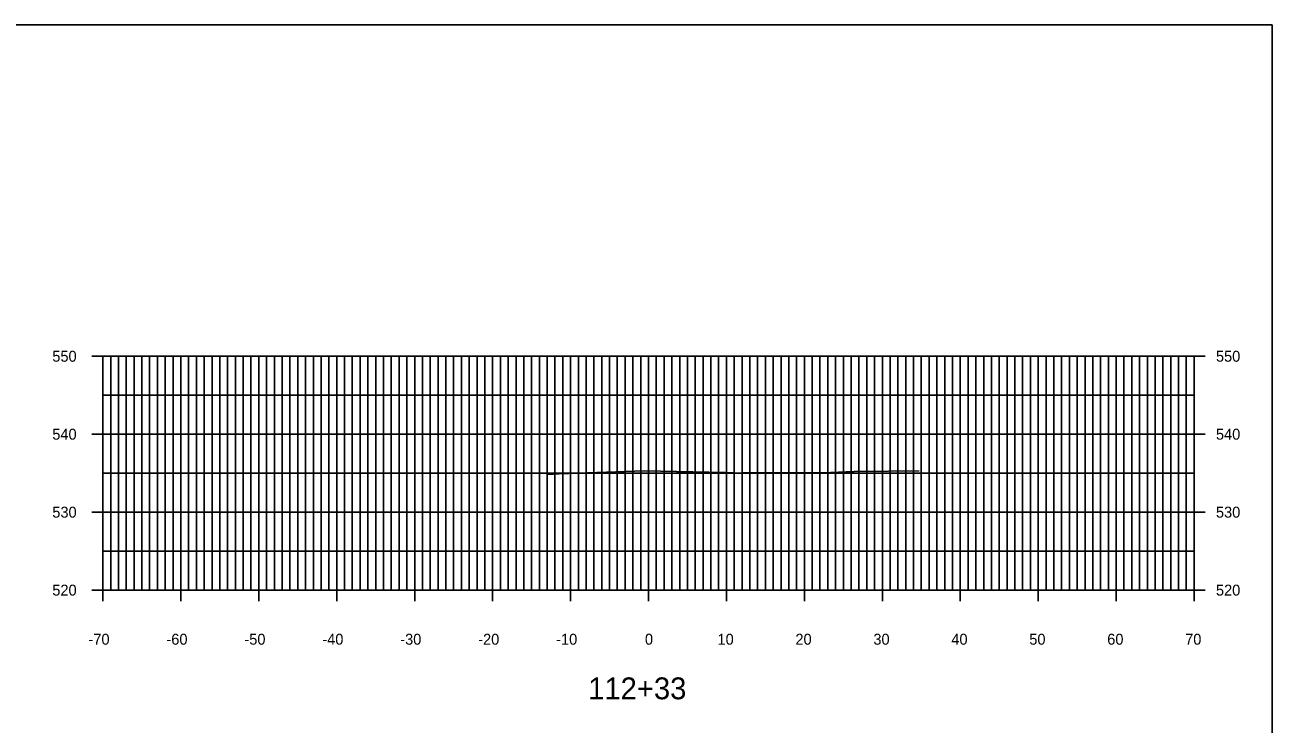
# Model space of a CAD drawing. Extents: x 1509063 to 1512863, y 401160 to 402918.
# Drawn here: x 1512702.7 to 1512862.7, y 402372.4 to 402462.1 of the extents above; entities that cross this region are included whole.
import ezdxf

# ---------------------------------------------------------------- set-up
doc = ezdxf.new("R2010")
doc.units = 0
for name, color, linetype in [('NBL1', 7, 'Continuous'), ('XAX_P', 7, 'Continuous'), ('XAXTIC_P', 7, 'Continuous'), ('XAXTXT_P_T', 7, 'Continuous'), ('XGL_P', 7, 'Continuous'), ('XSLOG', 7, 'Continuous')]:
    doc.layers.add(name, color=color, linetype=linetype)

msp = doc.modelspace()

# ---------------------------------------------------------------- linework, layer by layer
at = {"layer": 'NBL1'}
msp.add_lwpolyline([(1512862.73, 402252.08), (1512542.73, 402252.08), (1512542.73, 402462.08), (1512862.73, 402462.08)], close=True, dxfattribs=at)
at = {"layer": 'XAX_P'}
for p, q in [((1512712.73, 402389.58), (1512712.73, 402419.58)), ((1512782.73, 402389.58), (1512782.73, 402419.58)), ((1512852.73, 402389.58), (1512852.73, 402419.58)), ((1512712.73, 402389.58), (1512852.73, 402389.58))]:
    msp.add_line(p, q, dxfattribs=at)
at = {"layer": 'XAXTIC_P'}
for p, q in [((1512711.33, 402419.58), (1512714.13, 402419.58)), ((1512781.33, 402419.58), (1512784.13, 402419.58)), ((1512854.13, 402419.58), (1512851.33, 402419.58)), ((1512711.33, 402409.58), (1512714.13, 402409.58)), ((1512781.33, 402409.58), (1512784.13, 402409.58)), ((1512854.13, 402409.58), (1512851.33, 402409.58)), ((1512711.33, 402399.58), (1512714.13, 402399.58)), ((1512781.33, 402399.58), (1512784.13, 402399.58)), ((1512854.13, 402399.58), (1512851.33, 402399.58)), ((1512712.73, 402388.18), (1512712.73, 402390.98)), ((1512722.73, 402388.18), (1512722.73, 402390.98)), ((1512732.73, 402388.18), (1512732.73, 402390.98)), ((1512742.73, 402388.18), (1512742.73, 402390.98)), ((1512752.73, 402388.18), (1512752.73, 402390.98)), ((1512762.73, 402388.18), (1512762.73, 402390.98)), ((1512772.73, 402388.18), (1512772.73, 402390.98)), ((1512782.73, 402388.18), (1512782.73, 402390.98)), ((1512792.73, 402388.18), (1512792.73, 402390.98)), ((1512802.73, 402388.18), (1512802.73, 402390.98)), ((1512812.73, 402388.18), (1512812.73, 402390.98)), ((1512822.73, 402388.18), (1512822.73, 402390.98)), ((1512832.73, 402388.18), (1512832.73, 402390.98)), ((1512842.73, 402388.18), (1512842.73, 402390.98)), ((1512852.73, 402388.18), (1512852.73, 402390.98)), ((1512711.33, 402389.58), (1512714.13, 402389.58)), ((1512781.33, 402389.58), (1512784.13, 402389.58)), ((1512854.13, 402389.58), (1512851.33, 402389.58))]:
    msp.add_line(p, q, dxfattribs=at)
at = {"layer": 'XGL_P'}
for p, q in [((1512712.73, 402419.58), (1512852.73, 402419.58)), ((1512712.73, 402389.58), (1512712.73, 402419.58)), ((1512713.73, 402389.58), (1512713.73, 402419.58)), ((1512714.73, 402389.58), (1512714.73, 402419.58)), ((1512715.73, 402389.58), (1512715.73, 402419.58)), ((1512716.73, 402389.58), (1512716.73, 402419.58)), ((1512717.73, 402389.58), (1512717.73, 402419.58)), ((1512718.73, 402389.58), (1512718.73, 402419.58)), ((1512719.73, 402389.58), (1512719.73, 402419.58)), ((1512720.73, 402389.58), (1512720.73, 402419.58)), ((1512721.73, 402389.58), (1512721.73, 402419.58)), ((1512722.73, 402389.58), (1512722.73, 402419.58)), ((1512723.73, 402389.58), (1512723.73, 402419.58)), ((1512724.73, 402389.58), (1512724.73, 402419.58)), ((1512725.73, 402389.58), (1512725.73, 402419.58)), ((1512726.73, 402389.58), (1512726.73, 402419.58)), ((1512727.73, 402389.58), (1512727.73, 402419.58)), ((1512728.73, 402389.58), (1512728.73, 402419.58)), ((1512729.73, 402389.58), (1512729.73, 402419.58)), ((1512730.73, 402389.58), (1512730.73, 402419.58)), ((1512731.73, 402389.58), (1512731.73, 402419.58)), ((1512732.73, 402389.58), (1512732.73, 402419.58)), ((1512733.73, 402389.58), (1512733.73, 402419.58)), ((1512734.73, 402389.58), (1512734.73, 402419.58)), ((1512735.73, 402389.58), (1512735.73, 402419.58)), ((1512736.73, 402389.58), (1512736.73, 402419.58)), ((1512737.73, 402389.58), (1512737.73, 402419.58)), ((1512738.73, 402389.58), (1512738.73, 402419.58)), ((1512739.73, 402389.58), (1512739.73, 402419.58)), ((1512740.73, 402389.58), (1512740.73, 402419.58)), ((1512741.73, 402389.58), (1512741.73, 402419.58)), ((1512742.73, 402389.58), (1512742.73, 402419.58)), ((1512743.73, 402389.58), (1512743.73, 402419.58)), ((1512744.73, 402389.58), (1512744.73, 402419.58)), ((1512745.73, 402389.58), (1512745.73, 402419.58)), ((1512746.73, 402389.58), (1512746.73, 402419.58)), ((1512747.73, 402389.58), (1512747.73, 402419.58)), ((1512748.73, 402389.58), (1512748.73, 402419.58)), ((1512749.73, 402389.58), (1512749.73, 402419.58)), ((1512750.73, 402389.58), (1512750.73, 402419.58)), ((1512751.73, 402389.58), (1512751.73, 402419.58)), ((1512752.73, 402389.58), (1512752.73, 402419.58)), ((1512753.73, 402389.58), (1512753.73, 402419.58)), ((1512754.73, 402389.58), (1512754.73, 402419.58)), ((1512755.73, 402389.58), (1512755.73, 402419.58)), ((1512756.73, 402389.58), (1512756.73, 402419.58)), ((1512757.73, 402389.58), (1512757.73, 402419.58)), ((1512758.73, 402389.58), (1512758.73, 402419.58)), ((1512759.73, 402389.58), (1512759.73, 402419.58)), ((1512760.73, 402389.58), (1512760.73, 402419.58)), ((1512761.73, 402389.58), (1512761.73, 402419.58)), ((1512762.73, 402389.58), (1512762.73, 402419.58)), ((1512763.73, 402389.58), (1512763.73, 402419.58)), ((1512764.73, 402389.58), (1512764.73, 402419.58)), ((1512765.73, 402389.58), (1512765.73, 402419.58)), ((1512766.73, 402389.58), (1512766.73, 402419.58)), ((1512767.73, 402389.58), (1512767.73, 402419.58)), ((1512768.73, 402389.58), (1512768.73, 402419.58)), ((1512769.73, 402389.58), (1512769.73, 402419.58)), ((1512770.73, 402389.58), (1512770.73, 402419.58)), ((1512771.73, 402389.58), (1512771.73, 402419.58)), ((1512772.73, 402389.58), (1512772.73, 402419.58)), ((1512773.73, 402389.58), (1512773.73, 402419.58)), ((1512774.73, 402389.58), (1512774.73, 402419.58)), ((1512775.73, 402389.58), (1512775.73, 402419.58)), ((1512776.73, 402389.58), (1512776.73, 402419.58)), ((1512777.73, 402389.58), (1512777.73, 402419.58)), ((1512778.73, 402389.58), (1512778.73, 402419.58)), ((1512779.73, 402389.58), (1512779.73, 402419.58)), ((1512780.73, 402389.58), (1512780.73, 402419.58)), ((1512781.73, 402389.58), (1512781.73, 402419.58)), ((1512782.73, 402389.58), (1512782.73, 402419.58)), ((1512783.73, 402389.58), (1512783.73, 402419.58)), ((1512784.73, 402389.58), (1512784.73, 402419.58)), ((1512785.73, 402389.58), (1512785.73, 402419.58)), ((1512786.73, 402389.58), (1512786.73, 402419.58)), ((1512787.73, 402389.58), (1512787.73, 402419.58)), ((1512788.73, 402389.58), (1512788.73, 402419.58)), ((1512789.73, 402389.58), (1512789.73, 402419.58)), ((1512790.73, 402389.58), (1512790.73, 402419.58)), ((1512791.73, 402389.58), (1512791.73, 402419.58)), ((1512792.73, 402389.58), (1512792.73, 402419.58)), ((1512793.73, 402389.58), (1512793.73, 402419.58)), ((1512794.73, 402389.58), (1512794.73, 402419.58)), ((1512795.73, 402389.58), (1512795.73, 402419.58)), ((1512796.73, 402389.58), (1512796.73, 402419.58)), ((1512797.73, 402389.58), (1512797.73, 402419.58)), ((1512798.73, 402389.58), (1512798.73, 402419.58)), ((1512799.73, 402389.58), (1512799.73, 402419.58)), ((1512800.73, 402389.58), (1512800.73, 402419.58)), ((1512801.73, 402389.58), (1512801.73, 402419.58)), ((1512802.73, 402389.58), (1512802.73, 402419.58)), ((1512803.73, 402389.58), (1512803.73, 402419.58)), ((1512804.73, 402389.58), (1512804.73, 402419.58)), ((1512805.73, 402389.58), (1512805.73, 402419.58)), ((1512806.73, 402389.58), (1512806.73, 402419.58)), ((1512807.73, 402389.58), (1512807.73, 402419.58)), ((1512808.73, 402389.58), (1512808.73, 402419.58)), ((1512809.73, 402389.58), (1512809.73, 402419.58)), ((1512810.73, 402389.58), (1512810.73, 402419.58)), ((1512811.73, 402389.58), (1512811.73, 402419.58)), ((1512812.73, 402389.58), (1512812.73, 402419.58)), ((1512813.73, 402389.58), (1512813.73, 402419.58)), ((1512814.73, 402389.58), (1512814.73, 402419.58)), ((1512815.73, 402389.58), (1512815.73, 402419.58)), ((1512816.73, 402389.58), (1512816.73, 402419.58)), ((1512817.73, 402389.58), (1512817.73, 402419.58)), ((1512818.73, 402389.58), (1512818.73, 402419.58)), ((1512819.73, 402389.58), (1512819.73, 402419.58)), ((1512820.73, 402389.58), (1512820.73, 402419.58)), ((1512821.73, 402389.58), (1512821.73, 402419.58)), ((1512822.73, 402389.58), (1512822.73, 402419.58)), ((1512823.73, 402389.58), (1512823.73, 402419.58)), ((1512824.73, 402389.58), (1512824.73, 402419.58)), ((1512825.73, 402389.58), (1512825.73, 402419.58)), ((1512826.73, 402389.58), (1512826.73, 402419.58)), ((1512827.73, 402389.58), (1512827.73, 402419.58)), ((1512828.73, 402389.58), (1512828.73, 402419.58)), ((1512829.73, 402389.58), (1512829.73, 402419.58)), ((1512830.73, 402389.58), (1512830.73, 402419.58)), ((1512831.73, 402389.58), (1512831.73, 402419.58)), ((1512832.73, 402389.58), (1512832.73, 402419.58)), ((1512833.73, 402389.58), (1512833.73, 402419.58)), ((1512834.73, 402389.58), (1512834.73, 402419.58)), ((1512835.73, 402389.58), (1512835.73, 402419.58)), ((1512836.73, 402389.58), (1512836.73, 402419.58)), ((1512837.73, 402389.58), (1512837.73, 402419.58)), ((1512838.73, 402389.58), (1512838.73, 402419.58)), ((1512839.73, 402389.58), (1512839.73, 402419.58)), ((1512840.73, 402389.58), (1512840.73, 402419.58)), ((1512841.73, 402389.58), (1512841.73, 402419.58)), ((1512842.73, 402389.58), (1512842.73, 402419.58)), ((1512843.73, 402389.58), (1512843.73, 402419.58)), ((1512844.73, 402389.58), (1512844.73, 402419.58)), ((1512845.73, 402389.58), (1512845.73, 402419.58)), ((1512846.73, 402389.58), (1512846.73, 402419.58)), ((1512847.73, 402389.58), (1512847.73, 402419.58)), ((1512848.73, 402389.58), (1512848.73, 402419.58)), ((1512849.73, 402389.58), (1512849.73, 402419.58)), ((1512850.73, 402389.58), (1512850.73, 402419.58)), ((1512851.73, 402389.58), (1512851.73, 402419.58)), ((1512852.73, 402389.58), (1512852.73, 402419.58)), ((1512712.73, 402414.58), (1512852.73, 402414.58)), ((1512712.73, 402409.58), (1512852.73, 402409.58)), ((1512712.73, 402404.58), (1512852.73, 402404.58)), ((1512712.73, 402399.58), (1512852.73, 402399.58)), ((1512712.73, 402394.58), (1512852.73, 402394.58)), ((1512712.73, 402389.58), (1512852.73, 402389.58))]:
    msp.add_line(p, q, dxfattribs=at)
at = {"layer": 'XSLOG'}
msp.add_lwpolyline([(1512769.75, 402404.42), (1512771.28, 402404.48), (1512782.19, 402404.87), (1512792.56, 402404.65), (1512793.81, 402404.62), (1512794.22, 402404.6), (1512794.72, 402404.61), (1512804.99, 402404.63), (1512805.04, 402404.63), (1512809.11, 402404.79), (1512813.5, 402404.84), (1512817.47, 402404.88)], dxfattribs=at)

# ---------------------------------------------------------------- texts
at = {"layer": 'XAXTXT_P_T'}
for s, height, p in [('550', 1.4, (1512706.24, 402418.88)), ('550', 1.4, (1512855.53, 402418.88)), ('540', 1.4, (1512706.24, 402408.88)), ('540', 1.4, (1512855.53, 402408.88)), ('530', 1.4, (1512706.24, 402398.88)), ('530', 1.4, (1512855.53, 402398.88)), ('520', 1.4, (1512706.24, 402388.88)), ('520', 1.4, (1512855.53, 402388.88)), ('-70', 1.4, (1512710.88, 402382.58)), ('-60', 1.4, (1512720.88, 402382.58)), ('-50', 1.4, (1512730.88, 402382.58)), ('-40', 1.4, (1512740.88, 402382.58)), ('-30', 1.4, (1512750.88, 402382.58)), ('-20', 1.4, (1512760.88, 402382.58)), ('-10', 1.4, (1512770.88, 402382.58)), ('0', 1.4, (1512782.27, 402382.58)), ('10', 1.4, (1512791.58, 402382.58)), ('20', 1.4, (1512801.58, 402382.58)), ('30', 1.4, (1512811.58, 402382.58)), ('40', 1.4, (1512821.58, 402382.58)), ('50', 1.4, (1512831.58, 402382.58)), ('60', 1.4, (1512841.58, 402382.58)), ('70', 1.4, (1512851.58, 402382.58)), ('112+33', 2.8, (1512774.99, 402375.58))]:
    msp.add_text(s, height=height, dxfattribs=at).set_placement(p)

doc.saveas('drawing.dxf')
